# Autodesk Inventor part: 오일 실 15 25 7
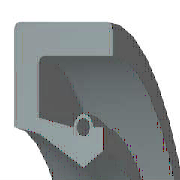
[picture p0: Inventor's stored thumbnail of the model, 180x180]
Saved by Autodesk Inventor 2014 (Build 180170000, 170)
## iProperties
Created: 2012-02
Part Number: 오일 실 15 25 7
Material: 고무
Description: 오일-실
Document SubType Name: Modeling
Standard: KS B 2804
Designer: mduedu
Standards Organization: KS
Language: ko-KR
Size Designation: S - 15 25 7
Categories: <MemberInstance><Categories><Category DisplayName="샤프트 부품" InternalName="7f7aeb1f-a693-4053-b835-cee3144e0d98" Mnemonic="SHFT"><Category DisplayName="실링" Intern
Density: 0.93 g/cm^3
Appearance: 고무 - 검은색 - 버전 1.1
IsCustomPart: 1
Author: mduedu
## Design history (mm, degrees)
revolve "본체" stored, may be unused: angle "d17" = 90 deg
revolve "스프링1" stored, may be unused: angle "d18" = 90 deg
body "Solid1"
sketch "스케치1"
  geometry: L1 (0, 12.5)-(7, 12.5); L2 (7, 12.5)-(7, 11.25); L3 (7, 11.25)-(1.75, 11.25); L4 (0, 12.5)-(0, 9.6); L5 (0, 9.6)-(1.75, 9.25); L6 (1.75, 9.25)-(4.9, 7.5); L7 (4.9, 7.5)-(0, 7.5); L8 (6.3, 8.375)-(6.3, 9.6); L9 (0, 0)-(9.586, 0) reference; L10 (4.9, 7.5)-(6.3, 8.375); L11 (0, 18)-(0, -3) reference; L12 (-1.917, 0)-(11.503, 0) reference; L13 (4.2, 9.6)-(1.75, 10.09); L14 (1.75, 10.09)-(1.75, 11.25); L15 (6.3, 9.6)-(5.6, 9.6); C1 r 0.455 at (4.9, 9.6); A1 r 0.7 centre (4.9, 9.6) between (5.6, 9.6) and (4.2, 9.6)
  constraints: 26 end point, 5 horizontal alignment, 4 perpendicular, 2 centre point, 2 collinear, 2 horizontal, 2 parallel, 2 point on circle, 2 point on line, 2 vertical alignment, 1 coincident
  dimensions: "d0" = 25 diameter of L1 L9 (= SD2); "d1" = 16.75 diameter of L8.start L9 (= ABDM); "d2" = 1.25 distance of L1.end L2.end (computed from SD); "d3" = 0.91 diameter of C1 (= SPDI); "d4" = 1.4 diameter of A1 (= SPDA); "d5" = 15 diameter of L6.end L9 (= NND); "d6" = 18.5 diameter of L5.end L9 (= TKDM); "d7" = 19.2 diameter of L4.end L9 (= HLDM); "d8" = 4.9 distance from line of C1.centre L4 (= SPDST); "d9" = 6.3 distance between parallel lines of L8 L4 (= SDI); "d10" = 7 distance between parallel lines of L2 L4 (= SWDT); "d12" = 1.75 distance between parallel lines of L14 L4 (= SD)
fillet "모깎기1" dims "d11" = 0.3 (= RR)
other parameters: "SD2" = 25 [user parameter; used in 1 equation term], "SWDT" = 7 [user parameter; used in 1 equation term], "RR" = 0.3 [user parameter; used in 1 equation term], "SD" = 1.75 [user parameter; used in 2 equation terms], "NND" = 15 [user parameter; used in 1 equation term], "SPDA" = 1.4 [user parameter; used in 1 equation term], "SPDI" = 0.91 [user parameter; used in 1 equation term], "TKDM" = 18.5 [user parameter; used in 1 equation term], "HLDM" = 19.2 [user parameter; used in 1 equation term], "ABDM" = 16.75 [user parameter; used in 1 equation term], "SDI" = 6.3 [user parameter; used in 1 equation term], "SPDST" = 4.9 [user parameter; used in 1 equation term], "d13" = 0, "d14" = 0, "d15" = 0, "LAB" = 0.35 [user parameter]
